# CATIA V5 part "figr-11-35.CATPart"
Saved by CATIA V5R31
Part number: Part1
Bounding box of the stored display mesh (mm): x -55 to 66, y 20 to 170, z -50 to 0
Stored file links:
  D:\PROJECTS\Project 2021\US EDITION\CATIA V5 6R 2021\Resources\Part Files\c11_catia_v5_6r2021_prt\figr-11-35.CATPart
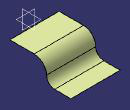
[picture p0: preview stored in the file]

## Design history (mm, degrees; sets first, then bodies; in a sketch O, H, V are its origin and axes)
Set1
  Extrude1: Element1 Sketch1, Lim1 66, Lim2 55, Direction yz-plane
  Symmetry1: ToTransfor Extrude1, Reference zx-plane
Body1 (main body)
  Sketch1 on yz-plane, origin (0, 0, 0), H (0, 1, 0), V (0, 0, 1)
    point P1 (20, 0)
    line L1 (20, 0) -> (80, 0)
    arc A1 centre (80, -30) radius 30 from (80, 0) to (110, -30) cw
    arc A2 centre (130, -30) radius 20 from (110, -30) to (130, -50) ccw
    line L2 (130, -50) -> (170, -50)
    coincidence: P1 H
    horizontal: L1 H
    tangency: A1 L1, A2 A1, L2 A2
